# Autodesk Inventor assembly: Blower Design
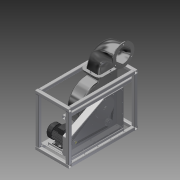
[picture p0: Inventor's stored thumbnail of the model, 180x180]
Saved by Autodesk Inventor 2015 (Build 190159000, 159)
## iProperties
Created: 2007-02
Part Number: Blower Design
Document SubType Name: Assembly
Designer: Autodesk, Inc.
Mass: 169749 g
Surface Area: 130158 cm^2
Volume: 38200.9 cm^3
Density: 4.44359 g/cm^3
_SolveAssemblyDoc: Frame Generator Solve Assembly
_Version: 15.0.0
Author: Autodesk, Inc.
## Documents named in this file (34)
- C:\Users\Public\Documents\Autodesk\Inventor 2015\Samples\Models\Assemblies\Blower\Blower.iam
- C:\Users\Public\Documents\Autodesk\Inventor 2015\Samples\Models\Assemblies\Blower\Components\SM - 001.ipt
- C:\Users\Public\Documents\Autodesk\Inventor 2015\Samples\Models\Assemblies\Blower\Components\SM - 002.ipt
- C:\Users\Public\Documents\Autodesk\Inventor 2015\Samples\Models\Assemblies\Blower\Components\Motor Assembly.iam
- C:\Users\Public\Documents\Autodesk\Inventor 2015\Samples\Models\Assemblies\Blower\Components\AL_Tube_01.ipt
- C:\Users\Public\Documents\Autodesk\Inventor 2015\Samples\Models\Assemblies\Blower\Components\Exhaust.iam
- C:\Users\Public\Documents\Autodesk\Inventor 2015\Samples\Models\Assemblies\Blower\Components\Drive Casing.ipt
- C:\Users\Public\Documents\Autodesk\Inventor 2015\Samples\Models\Assemblies\Blower\Components\Propeller.ipt
- C:\Users\Public\Documents\Autodesk\Inventor 2015\Samples\Models\Assemblies\Blower\Blower\Design Accelerator\Shaft1.iam
- C:\Users\Public\Documents\Autodesk\Inventor 2015\Samples\Models\Assemblies\Blower\Blower\Design Accelerator\V-Belt transmission1.iam
- C:\Users\Public\Documents\Autodesk\Inventor 2015\Samples\Models\Assemblies\Blower\Blower\Design Accelerator\Propeller Shaft Design1.iam
- C:\Users\Public\Documents\Autodesk\Inventor 2015\Samples\Models\Assemblies\Blower\Blower\Design Accelerator\Bolted Connection1.iam
- C:\Users\Public\Documents\Autodesk\Inventor 2015\Samples\Models\Assemblies\Blower\Blower\Design Accelerator\Key Connection2.iam
- C:\Users\Public\Documents\Autodesk\Inventor 2015\Samples\Standard Parts\en-US\ANSI B27.7(1)\ANSI B27.7 - 1310.3(1).ipt
- C:\Users\Public\Documents\Autodesk\Inventor 2015\Samples\Models\Assemblies\Blower\Blower\Design Accelerator\Bolted Connection Drive Casing1.iam
- C:\Users\Public\Documents\Autodesk\Inventor 2015\Samples\Models\Assemblies\Blower\Blower\Design Accelerator\Bolted Connection Motor Mount 11.iam
- C:\Users\Public\Documents\Autodesk\Inventor 2015\Samples\Models\Assemblies\Blower\Components\Frame Skeleton.ipt
- C:\Users\Public\Documents\Autodesk\Inventor 2015\Samples\Models\Assemblies\Blower\Blower\Frame\Blower Frame.iam
- C:\Users\Public\Documents\Autodesk\Inventor 2015\Samples\Models\Assemblies\Blower\Blower\Design Accelerator\Bolted Connection Exhaust Housing1.iam
- C:\Users\Public\Documents\Autodesk\Inventor 2015\Samples\Models\Assemblies\Blower\Blower\Design Accelerator\Bolted Connection Base Frame1.iam
- C:\Users\Public\Documents\Autodesk\Inventor 2015\Samples\Models\Assemblies\Blower\Blower\Design Accelerator\BC Exhaust 11.iam
- C:\Users\Public\Documents\Autodesk\Inventor 2015\Samples\Models\Assemblies\Blower\Blower\Design Accelerator\BC Exhaust 31.iam
- C:\Users\Public\Documents\Autodesk\Inventor 2015\Samples\Models\Assemblies\Blower\Blower\Design Accelerator\BC Exhaust 41.iam
- C:\Users\Public\Documents\Autodesk\Inventor 2015\Samples\Models\Assemblies\Blower\Blower\Design Accelerator\BC Exhaust 32.iam
- C:\Users\Public\Documents\Autodesk\Inventor 2015\Samples\Models\Assemblies\Blower\Blower\Design Accelerator\BC Motor Mount 11.iam
- C:\Users\Public\Documents\Autodesk\Inventor 2015\Samples\Models\Assemblies\Blower\Blower\Design Accelerator\BC Motor Mount 21.iam
- C:\Users\Public\Documents\Autodesk\Inventor 2015\Samples\Models\Assemblies\Blower\Blower\Design Accelerator\BC Motor Mount 31.iam
- C:\Users\Public\Documents\Autodesk\Inventor 2015\Samples\Models\Assemblies\Blower\Components\Drive Casing Cover.ipt
- C:\Users\Public\Documents\Autodesk\Inventor 2015\Samples\Models\Assemblies\Blower\Blower\Design Accelerator\Key Connection4.iam
- C:\Users\Public\Documents\Autodesk\Inventor 2015\Samples\Models\Assemblies\Blower\Blower\Design Accelerator\BC Motor Mount 41.iam
- C:\Users\Public\Documents\Autodesk\Inventor 2015\Samples\Models\Assemblies\Blower\Blower\Design Accelerator\BC Drive Lid 11.iam
- C:\Users\Public\Documents\Autodesk\Inventor 2015\Samples\Models\Assemblies\Blower\Blower\Design Accelerator\BC Drive Lid 21.iam
- C:\Users\Public\Documents\Autodesk\Inventor 2015\Samples\Models\Assemblies\Blower\Blower\Design Accelerator\BC Drive Lid 31.iam
- C:\Users\Public\Documents\Autodesk\Inventor 2015\Samples\Models\Assemblies\Blower\Blower\Design Accelerator\BC Drive Lid 41.iam
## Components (63 placed, 31 different names)
1. MA- 001:1 [sub-assembly] — Flush:1, Mate:45, Mate:46, Flush:11, Mate:77, Mate:78, Mate:79, Mate:80, Mate:81, Mate:82, Mate:83, Mate:84, Angle:12, Flush:19, Angle:17, Mate:88
2. SM - 001:2 — Mate:1, Mate:9, Flush:5, Flush:6, Mate:11, Flush:7, Mate:39, Mate:40
3. SM - 002:3 — Mate:1, Flush:1, Mate:43, Mate:44, Mate:46, Flush:11, Mate:48, Mate:49
4. CTube - 001 - Aluminum-6061:4 — Mate:24, Mate:25, Mate:26, Mate:69, Mate:70, Mate:71, Mate:72, Mate:73, Mate:74, Mate:75, Mate:76
5. EX - 1234:5 [sub-assembly] — Insert:2, Mate:9, Flush:5, Flush:6, Mate:10, Mate:24, Mate:25, Mate:26
6. Fan - 0062:6 — Insert:2, Mate:4, Mate:8, Flush:18
7. SM - 003:7 — Angle:1, Angle:2, Angle:3, Mate:10, Mate:11, Flush:7, Mate:15, Mate:16, Mate:45, Flush:13, Mate:60, Mate:62, Mate:64, Mate:66, Mate:68, Mate:87, Angle:15, Angle:16
8. Propeller Shaft Design:8 [sub-assembly] — Mate:8, Flush:17, Angle:13, Mate:86, Angle:14, Flush:18, Angle:16
9. V-Belt transmission:9 [sub-assembly] — Mate:13, Angle:12, Angle:14
10. Propeller Shaft Design:10 [sub-assembly] — Mate:13, Mate:87, Angle:15
11. Key Connection:17 [sub-assembly] — Flush:17, Angle:13, Mate:86
12. ANSI B27.7 - 13:18
13. Frame Skeleton:23
14. BF - 002:24 [sub-assembly]
15. BC Exhaust 1:35 [sub-assembly] — Mate:69, Mate:70
16. BC Exhaust 2:36 [sub-assembly] — Mate:71, Mate:72
17. BC Exhaust 4:37 [sub-assembly] — Mate:73, Mate:74
18. BC Exhaust 3:38 [sub-assembly] — Mate:75, Mate:76
19. BC Motor Mount 1:39 [sub-assembly] — Mate:77, Mate:78
20. BC Motor Mount 2:40 [sub-assembly] — Mate:79, Mate:80
21. BC Motor Mount 3:41 [sub-assembly] — Mate:81, Mate:82
22. BC Motor Mount 4:42 [sub-assembly] — Mate:83, Mate:84
23. SM - 004:43 — Flush:13, Mate:59, Mate:61, Mate:63, Mate:65, Mate:67
24. Key Connection:44 [sub-assembly] — Flush:19, Angle:17, Mate:88
25. Bolted Connection Drive Casing:11 [sub-assembly] — Mate:15, Mate:16
26. Bolted Connection Drive Casing:12 [sub-assembly]
27. Bolted Connection Drive Casing:13 [sub-assembly]
28. Bolted Connection Drive Casing:14 [sub-assembly]
29. Bolted Connection Drive Casing:15 [sub-assembly]
30. Bolted Connection Drive Casing:16 [sub-assembly]
31. Bolted Connection Motor Mount 1:19 [sub-assembly] — Mate:48, Mate:49
32. Bolted Connection Motor Mount 1:20 [sub-assembly]
33. Bolted Connection Motor Mount 2:21 [sub-assembly] — Mate:43, Mate:44
34. Bolted Connection Motor Mount 2:22 [sub-assembly]
35. Bolted Connection Base Frame:25 [sub-assembly] — Mate:39, Mate:40
36. Bolted Connection Base Frame:26 [sub-assembly]
37. Bolted Connection Base Frame:27 [sub-assembly]
38. Bolted Connection Base Frame:28 [sub-assembly]
39. Bolted Connection Base Frame:29 [sub-assembly]
40. Bolted Connection Base Frame:30 [sub-assembly]
41. Bolted Connection Base Frame:31 [sub-assembly]
42. Bolted Connection Base Frame:32 [sub-assembly]
43. Bolted Connection Base Frame:33 [sub-assembly]
44. Bolted Connection Base Frame:34 [sub-assembly]
45. BC Drive Lid 1:45 [sub-assembly] — Mate:59, Mate:60
46. BC Drive Lid 1:46 [sub-assembly]
47. BC Drive Lid 1:47 [sub-assembly]
48. BC Drive Lid 1:48 [sub-assembly]
49. BC Drive Lid 2:49 [sub-assembly] — Mate:61, Mate:62
50. BC Drive Lid 2:50 [sub-assembly]
51. BC Drive Lid 2:51 [sub-assembly]
52. BC Drive Lid 2:52 [sub-assembly]
53. BC Drive Lid 2:53 [sub-assembly]
54. BC Drive Lid 3:54 [sub-assembly] — Mate:63, Mate:64
55. BC Drive Lid 3:55 [sub-assembly]
56. BC Drive Lid 3:56 [sub-assembly]
57. BC Drive Lid 4:57 [sub-assembly] — Mate:65, Mate:66
58. BC Drive Lid 4:58 [sub-assembly]
59. BC Drive Lid 4:59 [sub-assembly]
60. BC Drive Lid 4:60 [sub-assembly]
61. BC Drive Lid 5:61 [sub-assembly] — Mate:67, Mate:68
62. BC Drive Lid 5:62 [sub-assembly]
63. BC Drive Lid 5:63 [sub-assembly]
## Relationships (68: Mate 49, Flush 9, Angle 9, Insert 1)
- Mate:1: SM - 001:2 ↔ SM - 002:3
- Flush:1: MA- 001:1 ↔ SM - 002:3
- Insert:2: EX - 1234:5 ↔ Fan - 0062:6
- Mate:4: Fan - 0062:6
- Angle:1: SM - 003:7
- Angle:2: SM - 003:7
- Angle:3: SM - 003:7
- Mate:8: Fan - 0062:6 ↔ Propeller Shaft Design:8
- Mate:9: SM - 001:2 ↔ EX - 1234:5
- Flush:5: SM - 001:2 ↔ EX - 1234:5
- Flush:6: SM - 001:2 ↔ EX - 1234:5
- Mate:10: EX - 1234:5 ↔ SM - 003:7
- Mate:11: SM - 001:2 ↔ SM - 003:7
- Flush:7: SM - 001:2 ↔ SM - 003:7
- Mate:13: V-Belt transmission:9 ↔ Propeller Shaft Design:10
- Mate:15: SM - 003:7 ↔ Bolted Connection Drive Casing:11
- Mate:16: SM - 003:7 ↔ Bolted Connection Drive Casing:11
- Mate:24: CTube - 001 - Aluminum-6061:4 ↔ EX - 1234:5
- Mate:25: CTube - 001 - Aluminum-6061:4 ↔ EX - 1234:5
- Mate:26: CTube - 001 - Aluminum-6061:4 ↔ EX - 1234:5
- Mate:39: SM - 001:2 ↔ Bolted Connection Base Frame:25
- Mate:40: SM - 001:2 ↔ Bolted Connection Base Frame:25
- Mate:43: SM - 002:3 ↔ Bolted Connection Motor Mount 2:21
- Mate:44: SM - 002:3 ↔ Bolted Connection Motor Mount 2:21
- Mate:45: MA- 001:1 ↔ SM - 003:7
- Mate:46: MA- 001:1 ↔ SM - 002:3
- Flush:11: MA- 001:1 ↔ SM - 002:3
- Mate:48: SM - 002:3 ↔ Bolted Connection Motor Mount 1:19
- Mate:49: SM - 002:3 ↔ Bolted Connection Motor Mount 1:19
- Flush:13: SM - 003:7 ↔ SM - 004:43
- Mate:59: SM - 004:43 ↔ BC Drive Lid 1:45
- Mate:60: SM - 003:7 ↔ BC Drive Lid 1:45
- Mate:61: SM - 004:43 ↔ BC Drive Lid 2:49
- Mate:62: SM - 003:7 ↔ BC Drive Lid 2:49
- Mate:63: SM - 004:43 ↔ BC Drive Lid 3:54
- Mate:64: SM - 003:7 ↔ BC Drive Lid 3:54
- Mate:65: SM - 004:43 ↔ BC Drive Lid 4:57
- Mate:66: SM - 003:7 ↔ BC Drive Lid 4:57
- Mate:67: SM - 004:43 ↔ BC Drive Lid 5:61
- Mate:68: SM - 003:7 ↔ BC Drive Lid 5:61
- Mate:69: CTube - 001 - Aluminum-6061:4 ↔ BC Exhaust 1:35
- Mate:70: CTube - 001 - Aluminum-6061:4 ↔ BC Exhaust 1:35
- Mate:71: CTube - 001 - Aluminum-6061:4 ↔ BC Exhaust 2:36
- Mate:72: CTube - 001 - Aluminum-6061:4 ↔ BC Exhaust 2:36
- Mate:73: CTube - 001 - Aluminum-6061:4 ↔ BC Exhaust 4:37
- Mate:74: CTube - 001 - Aluminum-6061:4 ↔ BC Exhaust 4:37
- Mate:75: CTube - 001 - Aluminum-6061:4 ↔ BC Exhaust 3:38
- Mate:76: CTube - 001 - Aluminum-6061:4 ↔ BC Exhaust 3:38
- Mate:77: MA- 001:1 ↔ BC Motor Mount 1:39
- Mate:78: MA- 001:1 ↔ BC Motor Mount 1:39
- Mate:79: MA- 001:1 ↔ BC Motor Mount 2:40
- Mate:80: MA- 001:1 ↔ BC Motor Mount 2:40
- Mate:81: MA- 001:1 ↔ BC Motor Mount 3:41
- Mate:82: MA- 001:1 ↔ BC Motor Mount 3:41
- Mate:83: MA- 001:1 ↔ BC Motor Mount 4:42
- Mate:84: MA- 001:1 ↔ BC Motor Mount 4:42
- Angle:12: MA- 001:1 ↔ V-Belt transmission:9
- Flush:17: Propeller Shaft Design:8 ↔ Key Connection:17
- Angle:13: Propeller Shaft Design:8 ↔ Key Connection:17
- Mate:86: Propeller Shaft Design:8 ↔ Key Connection:17
- Angle:14: Propeller Shaft Design:8 ↔ V-Belt transmission:9
- Mate:87: SM - 003:7 ↔ Propeller Shaft Design:10
- Angle:15: SM - 003:7 ↔ Propeller Shaft Design:10
- Flush:18: Fan - 0062:6 ↔ Propeller Shaft Design:8
- Angle:16: SM - 003:7 ↔ Propeller Shaft Design:8
- Flush:19: MA- 001:1 ↔ Key Connection:44
- Angle:17: MA- 001:1 ↔ Key Connection:44
- Mate:88: MA- 001:1 ↔ Key Connection:44
